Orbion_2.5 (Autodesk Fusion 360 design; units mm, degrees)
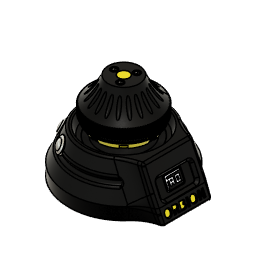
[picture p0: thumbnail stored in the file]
named bodies: "Corpo1", "Corpo2", "Corpo3", "Corpo4", "Corpo5", "Corpo6", "Corpo7", "Corpo8", "Corpo1 (1)", "Cushiion", "Insert 5x4_M3_1", "M3x8mm_1", "M3x8mm_2", "M3x8mm_3", "Insert 5x4_M3_2", "Nut_Encoder", "Strip", "led5", "led6", "led7", "led1", "led4", "led2", "led3", "Knob_Axis_17mm", "Enc_holder_17", "Knob_Bell_Short", "Body", "Insert 5x4_M3_4", "Insert 5x4_M3_3", "M3x15mm_1", "M3x15mm_2", "M3x10mm_2", "M3x10mm_3", "M3x15mm_3", "M3x10mm_1", "M3x10mm_4", "Shell", "MicroUSB", "Center_Bearings", "Type-C", "Wire_Clip_2", "Wire_Clip_1", "Support"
